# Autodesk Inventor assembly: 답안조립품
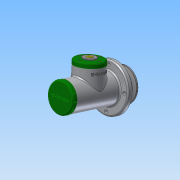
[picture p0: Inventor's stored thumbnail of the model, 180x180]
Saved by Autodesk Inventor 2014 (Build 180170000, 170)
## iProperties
Created: 2016-08
Part Number: 답안조립품
Document SubType Name: Assembly
Designer: 703
Author: 703
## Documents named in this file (25)
- C:\Users\703\Desktop\460807V1003\답안조립품.iam
- C:\Users\703\Desktop\460807V1003\V-벨트풀리.ipt
- C:\Users\703\Desktop\460807V1003\너트 M10.ipt
- C:\Users\703\Desktop\460807V1003\링크.ipt
- C:\Users\703\Desktop\460807V1003\멈춤링 15 x 1.ipt
- C:\Users\703\Desktop\460807V1003\멈춤링 35x1.6.ipt
- C:\Users\703\Desktop\460807V1003\베어링 15 x 35 x 11.ipt
- C:\Users\703\Desktop\460807V1003\본체.ipt
- C:\Users\703\Desktop\460807V1003\볼트 M4 x 10.ipt
- C:\Users\703\Desktop\460807V1003\볼트 M4 x 12.ipt
- C:\Users\703\Desktop\460807V1003\부시1.ipt
- C:\Users\703\Desktop\460807V1003\부시2.ipt
- C:\Users\703\Desktop\460807V1003\분할핀 1.6 x 12.ipt
- C:\Users\703\Desktop\460807V1003\사이드 커버.ipt
- 사이드 커버.ipt
- C:\Users\703\Desktop\460807V1003\슬라이더.ipt
- C:\Users\703\Desktop\460807V1003\오일 실 15 25 7.ipt
- C:\Users\703\Desktop\460807V1003\와셔 4x16.ipt
- C:\Users\703\Desktop\460807V1003\와셔 10x21.ipt
- C:\Users\703\Desktop\460807V1003\클래스터 핀 6 x 24.ipt
- C:\Users\703\Desktop\460807V1003\키 4 x 4 x 18.ipt
- C:\Users\703\Desktop\460807V1003\탑 부시.ipt
- C:\Users\703\Desktop\460807V1003\탑 커버.ipt
- 탑 커버.ipt
- C:\Users\703\Desktop\460807V1003\편심축.ipt
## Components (6 placed, 3 different names)
1. V-벨트풀리:1
2. ISO 4017 M4 x 10:1
3. ISO 4762 M4 x 12:1
4. ISO 4762 M4 x 12:2
5. ISO 4762 M4 x 12:3
6. ISO 4762 M4 x 12:4
